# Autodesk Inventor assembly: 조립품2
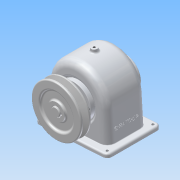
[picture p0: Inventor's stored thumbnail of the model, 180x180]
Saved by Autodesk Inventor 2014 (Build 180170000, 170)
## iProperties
Created: 2016-01
Part Number: 조립품2
Document SubType Name: Assembly
Designer: User
Author: User
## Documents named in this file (16)
- C:\Documents and Settings\User\My Documents\Inventor\460106V1018\답안조립품.iam
- C:\Documents and Settings\User\My Documents\Inventor\460106V1018\본체.ipt
- C:\Documents and Settings\User\My Documents\Inventor\460106V1018\축.ipt
- C:\Documents and Settings\User\My Documents\Inventor\460106V1018\뒤커버.ipt
- C:\Documents and Settings\User\My Documents\Inventor\460106V1018\베어링 6203.ipt
- C:\Documents and Settings\User\My Documents\Inventor\460106V1018\오일씰 28 40 8.ipt
- C:\Documents and Settings\User\My Documents\Inventor\460106V1018\부시1.ipt
- C:\Documents and Settings\User\My Documents\Inventor\460106V1018\부시2.ipt
- C:\Documents and Settings\User\My Documents\Inventor\460106V1018\스퍼기어.ipt
- C:\Documents and Settings\User\My Documents\Inventor\460106V1018\키 - 6 x 6 x 22.ipt
- C:\Documents and Settings\User\My Documents\Inventor\460106V1018\키 - 5 x 5 x 18.ipt
- C:\Documents and Settings\User\My Documents\Inventor\460106V1018\앞커버.ipt
- C:\Documents and Settings\User\My Documents\Inventor\460106V1018\V-벨트풀리.ipt
- C:\Documents and Settings\User\My Documents\Inventor\460106V1018\멈춤나사 - M4x10.ipt
- C:\Documents and Settings\User\My Documents\Inventor\460106V1018\볼트 M3 x 10.ipt
- C:\Documents and Settings\User\My Documents\Inventor\460106V1018\볼트 M3 x 8.ipt
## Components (9 placed, 3 different names)
1. V-벨트풀리:1
2. ISO 4762 M3 x 8:1
3. ISO 4762 M3 x 10:1
4. ISO 4762 M3 x 8:2
5. ISO 4762 M3 x 10:2
6. ISO 4762 M3 x 8:3
7. ISO 4762 M3 x 10:3
8. ISO 4762 M3 x 8:4
9. ISO 4762 M3 x 10:4
